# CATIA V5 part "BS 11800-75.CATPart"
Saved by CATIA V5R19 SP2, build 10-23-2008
Part number: BS 11800-75
Bounding box of the stored display mesh (mm): x -74.81 to 74.81, y -74.81 to 74.81, z 0 to 228
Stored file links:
  C:\Users\Bora\Desktop\3D Katı model\BS serisi\BS 11800\BS 11800-75.CATPart
  C:\Program Files\Dassault Systemes\B19\intel_a\reffiles\standard\MetricThickPitch.txt
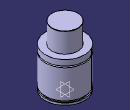
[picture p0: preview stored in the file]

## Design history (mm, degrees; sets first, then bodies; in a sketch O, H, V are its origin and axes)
Body1 (main body)
  Sketch1 on yz-plane, origin (0, 0, 0), H (0, 1, 0), V (0, 0, 1)
    point P1 (75, 130)
    point P2 (75, 125)
    point P5 (50, 227)
    point P7 (50, 227)
    point P12 (75, 125)
    point P13 (75, 130)
    arc A1 centre (75, 127.5) radius 2.5 from (75, 130) to (75, 125) ccw
    line L1 (75, 0) -> (75, 8)
    line L2 (50, 227) -> (50, 152)
    arc A2 centre (49, 227) radius 1 from (50, 227) to (49, 228) ccw
    line L3 (71, 15) -> (71, 8)
    line L4 (75, 15) -> (75, 125)
    line L5 (75, 130) -> (75, 152)
    line L6 (49, 228) -> (0, 228)
    point P15 (0, 228)
    line L7 (50, 152) -> (75, 152)
    line L8 (71, 15) -> (75, 15)
    line L9 (71, 8) -> (75, 8)
    line L10 (75, 0) -> (0, 0)
    coincidence: P15 V, P1 P13, P2 P12, P5 P7
    tangency: L6 A2
    horizontal: L7 H, L8 H, L9 H, L10 H
  Shaft1: profile Sketch1, axis Sketch1.V, angle 360
  Sketch2 on face of Shaft1 from Sketch1.L10, origin (0, 0, 0), H (1, 0, 0), V (0, -1, 0)
    point P1 (50, 0)
    distance P1 V = 50
  Hole1: placed by Sketch2, at (50, 0, 0) direction (0, 0, 1), diameter 8.376, depth 12, threaded "M10", thread diameter 10, thread depth 12, pitch 1.5
  CircPattern1: of Hole1, instances 4, angular step 90, axis from xy-plane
